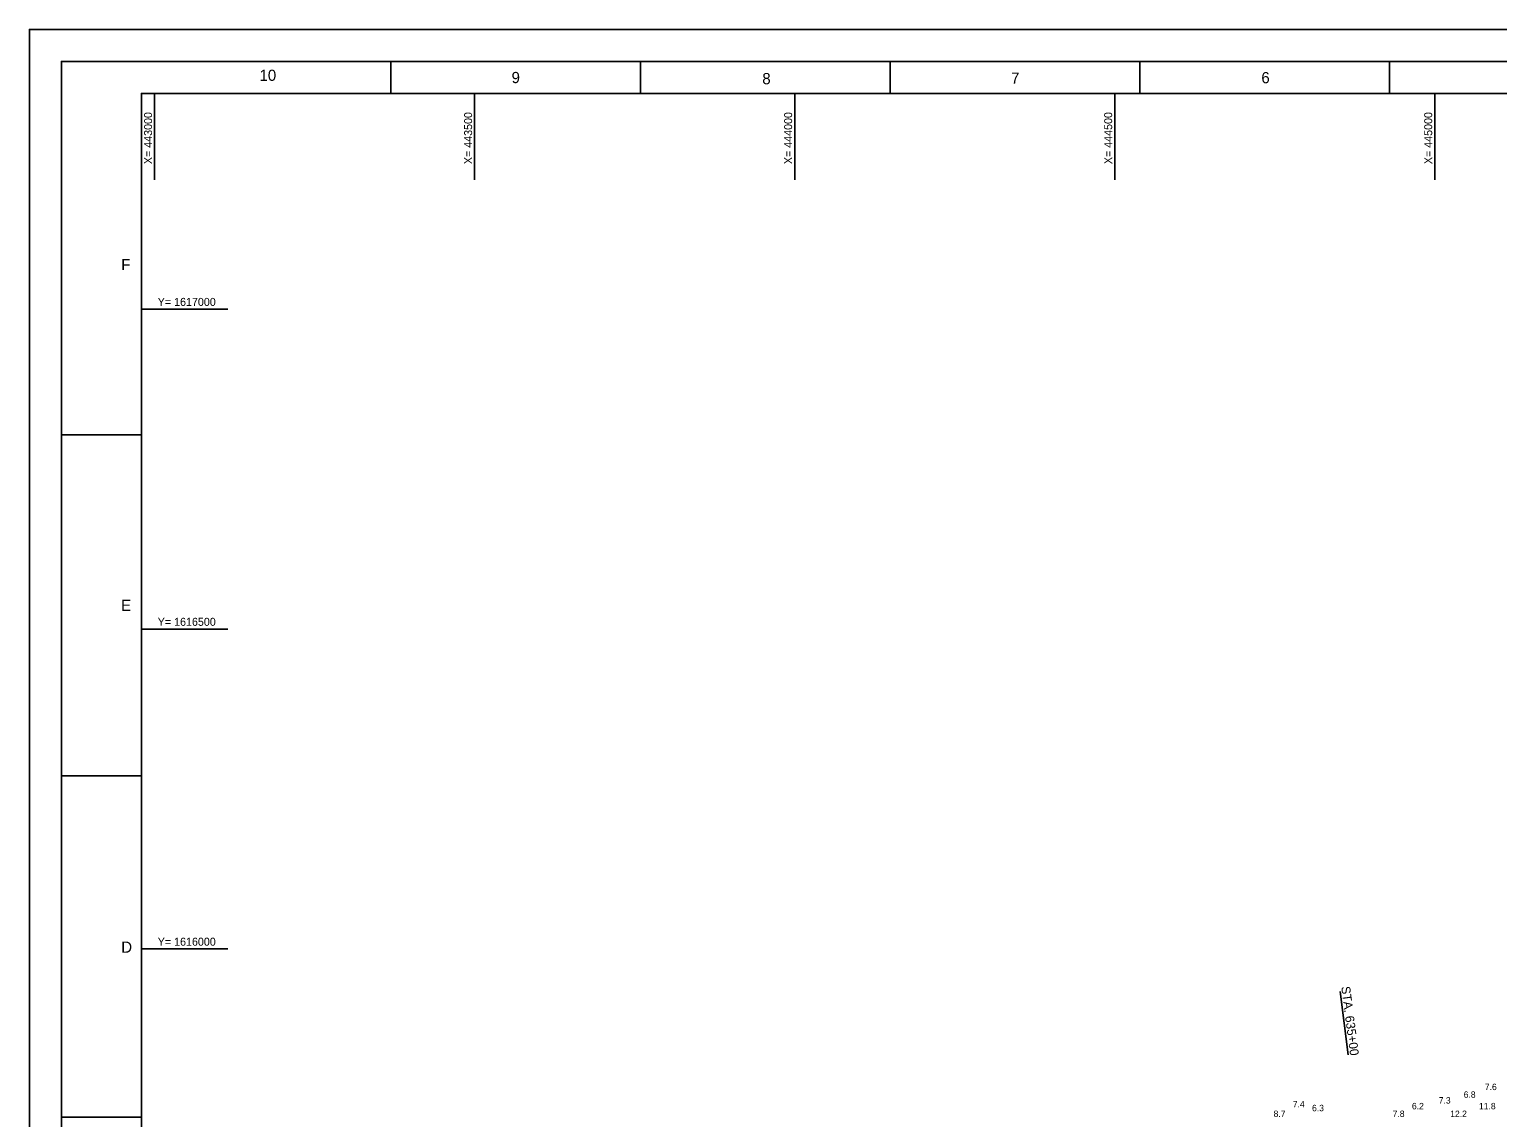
# Model space of a CAD drawing. Extents: x 442804 to 447204, y 1614037 to 1617437.
# Drawn here: x 442804 to 445098, y 1615736 to 1617437 of the extents above; entities that cross this region are included whole.
import ezdxf

# ---------------------------------------------------------------- set-up
doc = ezdxf.new("R2010")
doc.units = 0
for name, color, linetype in [('Default', 7, 'Continuous'), ('G-ANNO-NPLT', 7, 'Continuous'), ('G-ANNO-TTLB', 7, 'Continuous'), ('V-ALGN-TEXT', 7, 'Continuous'), ('V-TOPO-COOR-STAT', 7, 'Continuous')]:
    doc.layers.add(name, color=color, linetype=linetype)

msp = doc.modelspace()

# ---------------------------------------------------------------- linework, layer by layer
at = {"layer": 'G-ANNO-NPLT'}
msp.add_lwpolyline([(442804.3, 1617437.2), (447204.3, 1617437.2), (447204.3, 1614037.3), (442804.3, 1614037.3)], close=True, dxfattribs=at)
msp.add_lwpolyline([(442804.3, 1617387.2), (442804.3, 1617437.2), (442854.3, 1617437.2)], dxfattribs=at)
at = {"layer": 'G-ANNO-TTLB'}
for p, q in [((443369.3, 1617387.2), (443369.3, 1617337.2)), ((443759.3, 1617387.2), (443759.3, 1617337.2)), ((443759.3, 1617387.2), (443759.3, 1617337.2)), ((444149.3, 1617387.2), (444149.3, 1617337.2)), ((444539.3, 1617387.2), (444539.3, 1617337.2)), ((444929.3, 1617387.2), (444929.3, 1617337.2)), ((442854.3, 1616803.7), (442979.3, 1616803.7)), ((442854.3, 1616270.5), (442979.3, 1616270.5)), ((442854.3, 1615737.2), (442979.3, 1615737.2))]:
    msp.add_line(p, q, dxfattribs=at)
for points in [[(442854.3, 1614087.3), (447154.3, 1614087.3), (447154.3, 1617387.2), (442854.3, 1617387.2)], [(447104.3, 1617337.2), (442979.3, 1617337.2), (442979.3, 1614137.3), (447104.3, 1614137.3)]]:
    msp.add_lwpolyline(points, close=True, dxfattribs=at)
at = {"layer": 'V-ALGN-TEXT'}
msp.add_line((444852, 1615933.4), (444864.9, 1615834.3), dxfattribs=at)
at = {"layer": 'V-TOPO-COOR-STAT'}
for p, q in [((443000, 1617202.2), (443000, 1617337.2)), ((443500, 1617202.2), (443500, 1617337.2)), ((444000, 1617202.2), (444000, 1617337.2)), ((444500, 1617202.2), (444500, 1617337.2)), ((445000, 1617202.2), (445000, 1617337.2)), ((442979.3, 1617000), (443114.3, 1617000)), ((442979.3, 1616500), (443114.3, 1616500)), ((442979.3, 1616000), (443114.3, 1616000))]:
    msp.add_line(p, q, dxfattribs=at)

# ---------------------------------------------------------------- texts
at = {"layer": 'Default'}
for s, p in [('7.3', (445006.2, 1615758.3)), ('6.8', (445045.2, 1615767.3)), ('7.6', (445078.2, 1615779.3)), ('8.7', (444748.2, 1615737.3)), ('7.4', (444778.2, 1615752.3)), ('6.3', (444808.2, 1615746.3)), ('7.8', (444934.2, 1615737.3)), ('6.2', (444964.3, 1615749.3)), ('12.2 ', (445024.1, 1615737.3)), ('11.8 ', (445069.1, 1615749.3))]:
    msp.add_text(s, height=10, dxfattribs=at).set_placement(p)
at = {"layer": 'G-ANNO-TTLB'}
for s, p in [('10', (443163.9, 1617356.7)), ('9', (443557.7, 1617353.2)), ('8', (443949.4, 1617351.5)), ('7', (444338.1, 1617352.3)), ('6', (444729.1, 1617353)), ('F', (442947.9, 1617060.9)), ('E', (442947.7, 1616528.2)), ('D', (442947.9, 1615994))]:
    msp.add_text(s, height=17.5, dxfattribs=at).set_placement(p)
at = {"layer": 'V-ALGN-TEXT'}
msp.add_text('STA. 635+00', height=13.92, rotation=277.4167, dxfattribs=at).set_placement((444853.8, 1615940.8))
at = {"layer": 'V-TOPO-COOR-STAT'}
for s, p in [('X= 443000', (442996, 1617226.6)), ('X= 443500', (443496, 1617226.6)), ('X= 444000', (443996, 1617226.6)), ('X= 444500', (444496, 1617226.6)), ('X= 445000', (444996, 1617226.6))]:
    msp.add_text(s, height=12.5, rotation=90, dxfattribs=at).set_placement(p)
for s, p in [('Y= 1617000', (443004.9, 1617005)), ('Y= 1616500', (443004.9, 1616505)), ('Y= 1616000', (443004.9, 1616005))]:
    msp.add_text(s, height=12.5, dxfattribs=at).set_placement(p)

doc.saveas('drawing.dxf')
